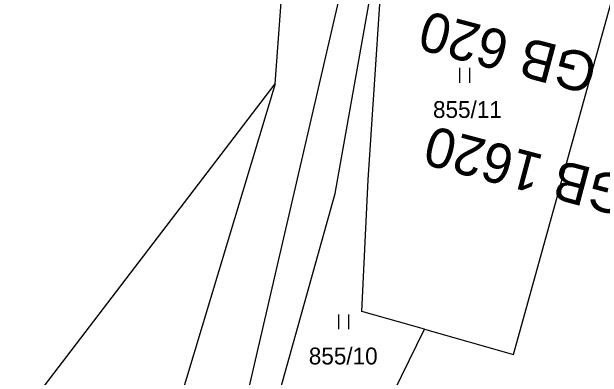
# Model space of a CAD drawing. Extents: x -7483133 to -743169, y -11317770 to -1127091.
# Drawn here: x -747630 to -747570.4, y -1131755.9 to -1131719 of the extents above; entities that cross this region are included whole.
import ezdxf

# ---------------------------------------------------------------- set-up
doc = ezdxf.new("R2010")
doc.units = 0
for name, color, linetype in [('bublina_fialová_čára_tenká', 7, 'Continuous'), ('Hranice parcel', 7, 'Continuous'), ('Parcelní čísla', 7, 'Continuous'), ('Značky kultur', 7, 'Continuous'), ('ŽBP', 7, 'Continuous')]:
    doc.layers.add(name, color=color, linetype=linetype)

msp = doc.modelspace()

# ---------------------------------------------------------------- linework, layer by layer
at = {"layer": 'bublina_fialová_čára_tenká'}
msp.add_line((-747611.38, -1131780.164), (-747594.166, -1131705.802), dxfattribs=at)
at = {"layer": 'Hranice parcel'}
for p, q in [((-747603.39, -1131726.29), (-747602.77, -1131718.05)), ((-747646.92, -1131783.21), (-747603.39, -1131726.29)), ((-747593.06, -1131760.75), (-747588.32, -1131751.04))]:
    msp.add_line(p, q, dxfattribs=at)
for points in [[(-747600.14, -1131761.43), (-747604.15, -1131761.78), (-747597.33, -1131737.34), (-747594.14, -1131719.37), (-747592.13, -1131708.07)], [(-747588.32, -1131751.04), (-747594.62, -1131749.25), (-747593.98, -1131735.96), (-747592.13, -1131708.07)], [(-747588.32, -1131751.04), (-747579.31, -1131753.61), (-747568.8, -1131715.62)], [(-747603.39, -1131726.29), (-747613.18, -1131758.77), (-747623.35, -1131774.87), (-747651.15, -1131801.66), (-747676.19, -1131826.81), (-747693.02, -1131845.21), (-747696.56, -1131853.11), (-747694.42, -1131867.19)]]:
    msp.add_lwpolyline(points, dxfattribs=at)
at = {"layer": 'Značky kultur'}
for p, q in [((-747584.731, -1131726.17), (-747584.731, -1131724.67)), ((-747583.73, -1131726.17), (-747583.73, -1131724.67)), ((-747596.941, -1131751.05), (-747596.941, -1131749.55)), ((-747595.94, -1131751.05), (-747595.94, -1131749.55))]:
    msp.add_line(p, q, dxfattribs=at)

# ---------------------------------------------------------------- texts
at = {"layer": 'Parcelní čísla'}
for s, p in [('855/11', (-747587.45, -1131729.72)), ('855/10', (-747599.99, -1131754.6))]:
    msp.add_text(s, height=1.7, dxfattribs=at).set_placement(p)
at = {"layer": 'ŽBP'}
for s, p in [('GB 620', (-747570.6, -1131723.515)), ('GB 1620', (-747567.206, -1131735.887))]:
    msp.add_text(s, height=3.9996, rotation=165.11843, dxfattribs=at).set_placement(p)

doc.saveas('drawing.dxf')
